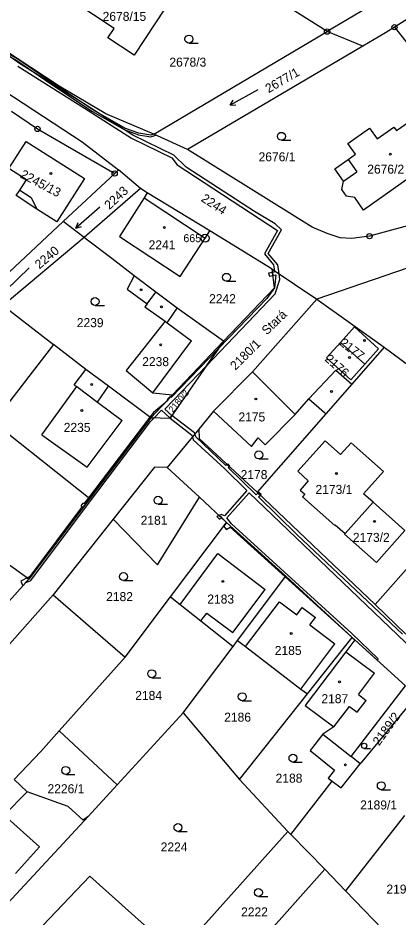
# Model space of a CAD drawing. Extents: x -562167 to -556918, y -1077891 to -1070763.
# Drawn here: x -560776.5 to -560704.7, y -1077589.8 to -1077420 of the extents above; entities that cross this region are included whole.
import ezdxf

# ---------------------------------------------------------------- set-up
doc = ezdxf.new("R2010")
doc.units = 0
for name, color, linetype in [('Hranice parcel', 7, 'Continuous'), ('Parcelní čísla', 7, 'Continuous'), ('Pop  PČ popisy', 7, 'Continuous'), ('Vnitřní kresba', 7, 'Continuous'), ('Věcná břemena k části', 7, 'Continuous'), ('Značky bodu BP', 7, 'Continuous'), ('Značky budov', 7, 'Continuous'), ('Značky kultur', 7, 'Continuous')]:
    doc.layers.add(name, color=color, linetype=linetype)

msp = doc.modelspace()

# ---------------------------------------------------------------- linework, layer by layer
at = {"layer": 'Hranice parcel'}
for p, q in [((-560718.13, -1077422.6), (-560741.25, -1077407.93)), ((-560750.84, -1077441.94), (-560718.13, -1077422.6)), ((-560711.41, -1077425.38), (-560718.13, -1077422.6)), ((-560711.41, -1077425.38), (-560744.45, -1077444.84)), ((-560744.45, -1077444.84), (-560750.84, -1077441.94)), ((-560757.47, -1077448.67), (-560758.22, -1077449.37)), ((-560753.37, -1077452.19), (-560757.47, -1077448.67)), ((-560758.22, -1077449.37), (-560767.94, -1077458.46)), ((-560753.37, -1077452.19), (-560763.95, -1077461.47)), ((-560752.08, -1077452.99), (-560753.37, -1077452.19)), ((-560740.26, -1077460.22), (-560752.08, -1077452.99)), ((-560767.94, -1077458.46), (-560778.08, -1077467.94)), ((-560763.95, -1077461.47), (-560767.94, -1077458.46)), ((-560728.52, -1077467.41), (-560740.26, -1077460.22)), ((-560763.95, -1077461.47), (-560779.27, -1077474.26)), ((-560697.73, -1077465.37), (-560720.07, -1077473.08)), ((-560728.52, -1077467.41), (-560720.07, -1077473.08)), ((-560779.27, -1077474.26), (-560769.74, -1077481.63)), ((-560720.07, -1077473.08), (-560707.36, -1077482.16)), ((-560747.28, -1077491.14), (-560737.69, -1077481.03)), ((-560711.02, -1077485.36), (-560715.6, -1077481.23)), ((-560769.74, -1077481.63), (-560781.07, -1077496.26)), ((-560707.36, -1077482.16), (-560682.61, -1077500.59)), ((-560751.4, -1077495.49), (-560747.28, -1077491.14)), ((-560739.56, -1077494.2), (-560742.36, -1077497.58)), ((-560718.37, -1077494.71), (-560731.36, -1077509.51)), ((-560781.07, -1077496.26), (-560762.93, -1077510.69)), ((-560762.93, -1077510.69), (-560751.4, -1077495.49)), ((-560742.36, -1077497.58), (-560748.29, -1077504.85)), ((-560748.29, -1077504.85), (-560742.24, -1077510.44)), ((-560731.36, -1077509.51), (-560709.04, -1077530.7)), ((-560774.45, -1077525.87), (-560762.93, -1077510.69)), ((-560742.24, -1077510.44), (-560737.1, -1077515.19)), ((-560714.73, -1077517.29), (-560709.46, -1077511.38)), ((-560758.48, -1077514.58), (-560769.81, -1077528.83)), ((-560747.68, -1077529.23), (-560737.1, -1077515.19)), ((-560737.1, -1077515.19), (-560725.93, -1077525.36)), ((-560696.13, -1077515.99), (-560709.04, -1077530.7)), ((-560774.45, -1077525.87), (-560782.82, -1077519.85)), ((-560735.04, -1077537.45), (-560725.93, -1077525.36)), ((-560725.93, -1077525.36), (-560713.41, -1077536.89)), ((-560769.81, -1077528.83), (-560756.25, -1077540.6)), ((-560756.25, -1077540.6), (-560747.68, -1077529.23)), ((-560709.04, -1077530.7), (-560703.28, -1077536.28)), ((-560721.86, -1077547.54), (-560713.41, -1077536.89)), ((-560713.41, -1077536.89), (-560712.89, -1077537.36)), ((-560712.89, -1077537.36), (-560703.35, -1077546.03)), ((-560745.31, -1077551.1), (-560735.88, -1077538.57)), ((-560735.88, -1077538.57), (-560735.04, -1077537.45)), ((-560756.25, -1077540.6), (-560768.67, -1077554.48)), ((-560734.66, -1077563.7), (-560721.86, -1077547.54)), ((-560701.28, -1077547.91), (-560711.88, -1077560.7)), ((-560757.75, -1077564.67), (-560745.31, -1077551.1)), ((-560745.31, -1077551.1), (-560734.66, -1077563.7)), ((-560768.67, -1077554.48), (-560757.75, -1077564.67)), ((-560734.66, -1077563.7), (-560725.53, -1077573.49)), ((-560724.98, -1077574.05), (-560717.2, -1077563.98)), ((-560757.75, -1077564.67), (-560763.25, -1077570.66)), ((-560703.5, -1077570.47), (-560714.63, -1077584.71)), ((-560725.53, -1077573.49), (-560744.02, -1077594.13)), ((-560725.53, -1077573.49), (-560724.98, -1077574.05)), ((-560718.57, -1077580.57), (-560724.98, -1077574.05)), ((-560718.57, -1077580.57), (-560733.72, -1077597.56)), ((-560714.63, -1077584.71), (-560718.57, -1077580.57)), ((-560714.63, -1077584.71), (-560705.92, -1077593.73))]:
    msp.add_line(p, q, dxfattribs=at)
for points in [[(-560877.62, -1077369.81), (-560869.17, -1077375.64), (-560821.56, -1077405.93), (-560764.33, -1077443.43), (-560757.47, -1077448.67)], [(-560668.72, -1077392.43), (-560686.84, -1077410.17), (-560705.42, -1077421.78)], [(-560758.31, -1077422), (-560766.1, -1077416.89), (-560761.45, -1077409.83), (-560748.66, -1077418.18), (-560754.53, -1077427.07), (-560759.49, -1077423.81), (-560758.31, -1077422)], [(-560705.88, -1077415.05), (-560710.42, -1077418.05), (-560718.13, -1077422.6)], [(-560750.84, -1077441.94), (-560759.89, -1077438.13), (-560768.71, -1077432.87), (-560787.2, -1077420.77)], [(-560705.42, -1077421.78), (-560707.11, -1077422.85), (-560711.41, -1077425.38)], [(-560705.42, -1077421.78), (-560691.8, -1077438.94), (-560686.3, -1077445)], [(-560777.7, -1077437.59), (-560772.79, -1077440.96), (-560758.22, -1077449.37)], [(-560695.32, -1077444.21), (-560700.44, -1077447.78), (-560700.05, -1077448.39), (-560711.25, -1077456.28), (-560712.91, -1077453.92), (-560714.45, -1077453.63), (-560715.32, -1077452.4), (-560715.05, -1077450.85), (-560716.69, -1077448.51), (-560714.16, -1077446.72), (-560712.77, -1077445.74), (-560714.2, -1077443.69), (-560710.11, -1077440.81), (-560708.66, -1077442.84), (-560705.51, -1077440.62), (-560705.02, -1077441.25), (-560699.9, -1077437.67), (-560695.32, -1077444.21)], [(-560776.11, -1077452.52), (-560774.86, -1077450.56), (-560778.19, -1077448.46), (-560774.9, -1077443.33), (-560763.93, -1077450.3), (-560769.13, -1077458.47), (-560772.89, -1077456.08), (-560776.78, -1077453.53), (-560776.11, -1077452.52)], [(-560685.68, -1077455.18), (-560689.59, -1077455.62), (-560710.13, -1077461.19), (-560713.49, -1077461.63), (-560715.68, -1077461.51), (-560718.09, -1077460.7), (-560720.94, -1077459.48), (-560744.45, -1077444.84)], [(-560752.08, -1077452.99), (-560752.68, -1077453.94), (-560757.32, -1077461.28), (-560745.85, -1077468.78), (-560741.15, -1077461.58), (-560740.26, -1077460.22)], [(-560754.57, -1077468.7), (-560758.77, -1077465.38), (-560763.57, -1077461.75), (-560763.95, -1077461.47)], [(-560737.69, -1077481.03), (-560728.04, -1077470.93), (-560728.52, -1077467.41)], [(-560754.57, -1077468.7), (-560755.89, -1077471.18), (-560752.1, -1077473.97), (-560752.51, -1077474.51), (-560748.68, -1077477.24), (-560756.03, -1077486.53), (-560751, -1077490.72), (-560747.28, -1077491.14)], [(-560737.69, -1077481.03), (-560746.4, -1077474.75), (-560750.45, -1077471.75), (-560754.57, -1077468.7)], [(-560720.07, -1077473.08), (-560732.22, -1077486.79), (-560739.56, -1077494.2)], [(-560715.6, -1077481.23), (-560712.99, -1077478.31), (-560708.41, -1077482.46), (-560711.02, -1077485.36)], [(-560737.69, -1077481.03), (-560747.84, -1077495.6), (-560751.4, -1077495.49)], [(-560711.02, -1077485.36), (-560713.64, -1077488.27), (-560718.23, -1077484.16), (-560715.6, -1077481.23)], [(-560751.4, -1077495.49), (-560759.39, -1077489.52), (-560763.68, -1077486.32), (-560769.74, -1077481.63)], [(-560707.36, -1077482.16), (-560713.48, -1077489.14), (-560718.37, -1077494.71)], [(-560739.56, -1077494.2), (-560732.41, -1077500.9), (-560731.17, -1077499.22), (-560729.82, -1077500.56), (-560724.13, -1077494.81), (-560721.58, -1077491.87), (-560718.63, -1077494.48), (-560718.37, -1077494.71)], [(-560742.36, -1077497.58), (-560742.29, -1077499.35), (-560731.36, -1077509.51)], [(-560709.46, -1077511.38), (-560711.27, -1077509.77), (-560707.51, -1077505.61), (-560713.61, -1077500.21), (-560715.59, -1077502.41), (-560718.49, -1077499.79), (-560723.68, -1077505.55), (-560721.68, -1077507.36), (-560723.24, -1077509.08), (-560722.35, -1077509.89), (-560722.76, -1077510.34), (-560716.67, -1077515.77), (-560716.58, -1077515.64), (-560714.73, -1077517.29)], [(-560748.29, -1077504.85), (-560750.68, -1077504.78), (-560758.48, -1077514.58)], [(-560758.48, -1077514.58), (-560750.12, -1077523.2), (-560742.24, -1077510.44)], [(-560714.73, -1077517.29), (-560714.83, -1077517.39), (-560708.83, -1077522.74), (-560703.46, -1077516.72), (-560709.46, -1077511.38)], [(-560795.12, -1077548.97), (-560794.92, -1077548.75), (-560774.45, -1077525.87)], [(-560769.81, -1077528.83), (-560803.23, -1077566.5), (-560803.72, -1077567.05)], [(-560747.68, -1077529.23), (-560745.88, -1077530.65), (-560741.95, -1077533.77), (-560735.88, -1077538.57)], [(-560712.89, -1077537.36), (-560714.62, -1077539.63), (-560722.28, -1077549.71), (-560716.84, -1077553.73), (-560718.96, -1077555.14), (-560721.35, -1077558.24), (-560716.73, -1077561.9), (-560717.9, -1077563.45), (-560717.2, -1077563.98)], [(-560735.04, -1077537.45), (-560733.55, -1077538.59), (-560723.06, -1077546.62), (-560721.86, -1077547.54)], [(-560711.88, -1077560.7), (-560713.62, -1077559.33), (-560703.35, -1077546.03)], [(-560777.2, -1077563.69), (-560772.17, -1077558.4), (-560768.67, -1077554.48)], [(-560717.2, -1077563.98), (-560715.49, -1077565.27), (-560711.88, -1077560.7)], [(-560763.25, -1077570.66), (-560764.19, -1077571.35), (-560767.01, -1077568.77), (-560774.76, -1077565.99), (-560777.2, -1077563.69)], [(-560763.25, -1077570.66), (-560767.95, -1077575.79), (-560780.07, -1077588.79)], [(-560746.38, -1077596.77), (-560748.38, -1077594.93), (-560762.88, -1077581.89), (-560774.38, -1077593.94)]]:
    msp.add_lwpolyline(points, dxfattribs=at)
at = {"layer": 'Vnitřní kresba'}
for p, q in [((-560714.16, -1077446.72), (-560712.49, -1077449.09)), ((-560715.05, -1077450.85), (-560712.49, -1077449.09)), ((-560776.11, -1077452.52), (-560773.96, -1077453.9)), ((-560773.96, -1077453.9), (-560772.89, -1077456.08)), ((-560752.68, -1077453.94), (-560741.15, -1077461.58)), ((-560752.1, -1077473.97), (-560750.45, -1077471.75)), ((-560748.29, -1077477.54), (-560746.4, -1077474.75)), ((-560748.68, -1077477.24), (-560748.29, -1077477.54)), ((-560748.29, -1077477.54), (-560743.75, -1077480.94)), ((-560751, -1077490.72), (-560743.75, -1077480.94)), ((-560765.84, -1077489.21), (-560763.68, -1077486.32)), ((-560732.22, -1077486.79), (-560724.13, -1077494.81)), ((-560721.58, -1077491.87), (-560716.5, -1077486.5)), ((-560716.5, -1077486.5), (-560713.48, -1077489.14)), ((-560771.99, -1077498.68), (-560765.36, -1077489.57)), ((-560765.84, -1077489.21), (-560765.36, -1077489.57)), ((-560765.36, -1077489.57), (-560761.47, -1077492.48)), ((-560761.47, -1077492.48), (-560759.39, -1077489.52)), ((-560761.47, -1077492.48), (-560756.8, -1077495.98)), ((-560763.41, -1077504.75), (-560756.8, -1077495.98)), ((-560771.99, -1077498.68), (-560763.41, -1077504.75)), ((-560745.88, -1077530.65), (-560738.73, -1077521.08)), ((-560738.73, -1077521.08), (-560729.81, -1077527.82)), ((-560735.89, -1077535.93), (-560729.81, -1077527.82)), ((-560733.55, -1077538.59), (-560727.11, -1077530.18)), ((-560727.11, -1077530.18), (-560723.87, -1077532.64)), ((-560723.87, -1077532.64), (-560722.82, -1077531.26)), ((-560722.82, -1077531.26), (-560720.32, -1077533.13)), ((-560741.95, -1077533.77), (-560740.81, -1077532.33)), ((-560740.81, -1077532.33), (-560735.89, -1077535.93)), ((-560721.38, -1077534.53), (-560720.32, -1077533.13)), ((-560721.38, -1077534.53), (-560716.7, -1077538.08)), ((-560723.06, -1077546.62), (-560716.7, -1077538.08)), ((-560714.62, -1077539.63), (-560709.18, -1077543.63)), ((-560712.22, -1077547.63), (-560709.18, -1077543.63)), ((-560712.46, -1077551.01), (-560710.73, -1077548.76)), ((-560712.22, -1077547.63), (-560710.73, -1077548.76)), ((-560716.84, -1077553.73), (-560713.93, -1077549.89)), ((-560713.93, -1077549.89), (-560712.46, -1077551.01)), ((-560718.96, -1077555.14), (-560713.62, -1077559.33)), ((-560779.06, -1077570.4), (-560774.76, -1077565.99)), ((-560779.06, -1077570.4), (-560772.4, -1077576.37)), ((-560776.92, -1077581.4), (-560772.4, -1077576.37))]:
    msp.add_line(p, q, dxfattribs=at)
at = {"layer": 'Věcná břemena k části'}
for points in [[(-560786, -1077421.56), (-560787.2, -1077420.77), (-560787.62, -1077420.5), (-560787.72, -1077420.66), (-560787.36, -1077420.89), (-560786.75, -1077422.28), (-560784.02, -1077423.94), (-560776.67, -1077428.04), (-560770.27, -1077432.44), (-560762.38, -1077437.71), (-560756.3, -1077441.14), (-560753.75, -1077442.06), (-560751.37, -1077442.48), (-560750.43, -1077442.12), (-560750.84, -1077441.94), (-560751.39, -1077442.17), (-560753.67, -1077441.76), (-560756.18, -1077440.86), (-560762.22, -1077437.45), (-560770.11, -1077432.2), (-560776.51, -1077427.78), (-560783.88, -1077423.68), (-560786.38, -1077422.16)], [(-560728.36, -1077468.61), (-560728.44, -1077468.02), (-560729.18, -1077468.15), (-560729.01, -1077468.73)], [(-560748.67, -1077492.61), (-560750.88, -1077494.44), (-560751.57, -1077495.36), (-560751.4, -1077495.49), (-560750.81, -1077495.51), (-560749.4, -1077494.02), (-560747.77, -1077495.5), (-560747.43, -1077495.01), (-560748.74, -1077493.82), (-560740.9, -1077485.63), (-560738.59, -1077482.32), (-560747.57, -1077491.61), (-560747.65, -1077491.53), (-560747.77, -1077491.41), (-560748.3, -1077491.99), (-560748.18, -1077492.09), (-560748.12, -1077492.15)], [(-560750.81, -1077495.51), (-560751.4, -1077495.49), (-560762.93, -1077510.69), (-560774.45, -1077525.87), (-560775.08, -1077526.58), (-560774.02, -1077526.14), (-560763.7, -1077512.35), (-560751.44, -1077496.18)], [(-560751.57, -1077495.36), (-560763.13, -1077510.53), (-560762.93, -1077510.69), (-560751.4, -1077495.49)], [(-560737.02, -1077504.25), (-560736.57, -1077504.66), (-560736.46, -1077504.56), (-560736.88, -1077504.13)], [(-560731.19, -1077509.67), (-560730.75, -1077510.09), (-560730.59, -1077509.94), (-560731.02, -1077509.52)], [(-560774.73, -1077525.67), (-560774.45, -1077525.87), (-560762.93, -1077510.69), (-560763.13, -1077510.53), (-560764.03, -1077511.71), (-560764.22, -1077511.56), (-560764.58, -1077512.04), (-560764.35, -1077512.22), (-560774.21, -1077525.4)], [(-560738.46, -1077514.55), (-560738.02, -1077514.34), (-560738.5, -1077513.9), (-560738.91, -1077514.09)], [(-560726.02, -1077525.47), (-560725.93, -1077525.36), (-560737.1, -1077515.19), (-560737.64, -1077515.91), (-560737.15, -1077516.55), (-560736.4, -1077516.06)], [(-560713.41, -1077536.89), (-560725.93, -1077525.36), (-560726.02, -1077525.47)], [(-560775.95, -1077526.28), (-560775.58, -1077527.13), (-560774.45, -1077525.87), (-560774.73, -1077525.67)]]:
    msp.add_lwpolyline(points, close=True, dxfattribs=at)
for points in [[(-560776.52, -1077429.14), (-560763.9, -1077437.02), (-560755.05, -1077442.69), (-560747.45, -1077446.43), (-560746.45, -1077447.77), (-560727.47, -1077460.12), (-560729.96, -1077464.54), (-560728.23, -1077466.6), (-560728.07, -1077467.71), (-560728.03, -1077467.94), (-560728.44, -1077468.02), (-560728.36, -1077468.61), (-560727.8, -1077468.51), (-560728.04, -1077470.93), (-560729.51, -1077472.93), (-560738.59, -1077482.32), (-560740.9, -1077485.63), (-560727.92, -1077472.08), (-560727.03, -1077469.39), (-560727.18, -1077468.31), (-560727.43, -1077466.62), (-560729.23, -1077464.47), (-560726.73, -1077460.02), (-560727.91, -1077458.89), (-560731.82, -1077456.57), (-560744.74, -1077448.17), (-560747.07, -1077445.94), (-560754.77, -1077442.16), (-560763.58, -1077436.51), (-560776.19, -1077428.63), (-560782.13, -1077424.44)], [(-560703.93, -1077536.26), (-560723.8, -1077517.56), (-560731.08, -1077510.38), (-560730.75, -1077510.09), (-560731.19, -1077509.67), (-560731.52, -1077509.97), (-560736.78, -1077504.85), (-560736.57, -1077504.66), (-560737.02, -1077504.25), (-560737.26, -1077504.48), (-560742.92, -1077499.07), (-560743.11, -1077498.5), (-560743.17, -1077498.3), (-560747.43, -1077495.01), (-560747.77, -1077495.5), (-560743.69, -1077498.66), (-560743.56, -1077499.05), (-560743.38, -1077499.6), (-560737.41, -1077505.07), (-560733.3, -1077509.18), (-560737.49, -1077513.92), (-560738.05, -1077513.69), (-560738.5, -1077513.9), (-560738.02, -1077514.34), (-560737.1, -1077515.19), (-560725.93, -1077525.36), (-560713.41, -1077536.89), (-560712.89, -1077537.36), (-560708.62, -1077541.24), (-560708.47, -1077540.91), (-560713.47, -1077536.12), (-560736.17, -1077515.47), (-560737.05, -1077514.32), (-560732.86, -1077509.6), (-560701.87, -1077539.21)]]:
    msp.add_lwpolyline(points, dxfattribs=at)
at = {"layer": 'Značky bodu BP'}
for centre, radius in [((-560705.42, -1077421.78), 0.5), ((-560705.42, -1077421.78), 0.0303), ((-560718.13, -1077422.6), 0.5), ((-560718.13, -1077422.6), 0.0303), ((-560772.79, -1077440.96), 0.5), ((-560772.79, -1077440.96), 0.0303), ((-560758.22, -1077449.37), 0.5), ((-560758.22, -1077449.37), 0.0303), ((-560741.15, -1077461.58), 0.75), ((-560710.13, -1077461.19), 0.5), ((-560741.15, -1077461.58), 0.03), ((-560710.13, -1077461.19), 0.0303)]:
    msp.add_circle(centre, radius, dxfattribs=at)
at = {"layer": 'Značky budov'}
for centre in [(-560706.2, -1077445.74), (-560770.24, -1077449.38), (-560748.85, -1077459.55), (-560753.24, -1077471.3), (-560749.41, -1077474.51), (-560711.1, -1077480.87), (-560749.54, -1077481.71), (-560713.89, -1077484.07), (-560762.56, -1077489.18), (-560717.3, -1077490.5), (-560731.59, -1077491.91), (-560764.4, -1077494.08), (-560716.38, -1077505.95), (-560709.19, -1077515), (-560737.78, -1077526.31), (-560724.89, -1077536.16), (-560715.8, -1077545.26), (-560714.69, -1077560.93)]:
    msp.add_circle(centre, 0.175, dxfattribs=at)
at = {"layer": 'Značky kultur'}
for p, q in [((-560744.2, -1077424.78), (-560742.45, -1077424.78)), ((-560731.2, -1077433.58), (-560736.44, -1077436.49)), ((-560736.44, -1077436.49), (-560735.83, -1077435.57)), ((-560736.44, -1077436.49), (-560735.34, -1077436.45)), ((-560726.75, -1077443.11), (-560725, -1077443.11)), ((-560761.02, -1077455.73), (-560765.55, -1077459.66)), ((-560765.55, -1077459.66), (-560765.14, -1077458.64)), ((-560765.55, -1077459.66), (-560764.49, -1077459.4)), ((-560774.35, -1077467.19), (-560778.67, -1077471.36)), ((-560737.11, -1077469.71), (-560735.36, -1077469.71)), ((-560761.92, -1077474.27), (-560760.17, -1077474.27)), ((-560731.02, -1077503.22), (-560729.27, -1077503.22)), ((-560750.03, -1077511.76), (-560748.28, -1077511.76)), ((-560756.55, -1077526.16), (-560754.8, -1077526.16)), ((-560751.23, -1077544.48), (-560749.48, -1077544.48)), ((-560734.14, -1077548.83), (-560732.39, -1077548.83)), ((-560711.12, -1077557.83), (-560709.95, -1077557.83)), ((-560724.57, -1077560.41), (-560722.82, -1077560.41)), ((-560767.46, -1077562.73), (-560765.71, -1077562.73)), ((-560707.9, -1077565.62), (-560706.15, -1077565.62)), ((-560746.27, -1077573.49), (-560744.52, -1077573.49)), ((-560731.09, -1077585.75), (-560729.34, -1077585.75))]:
    msp.add_line(p, q, dxfattribs=at)
for centre, radius in [((-560744.2, -1077424.03), 0.75), ((-560726.75, -1077442.36), 0.75), ((-560737.11, -1077468.96), 0.75), ((-560761.92, -1077473.52), 0.75), ((-560731.02, -1077502.47), 0.75), ((-560750.03, -1077511.01), 0.75), ((-560756.55, -1077525.41), 0.75), ((-560751.23, -1077543.73), 0.75), ((-560734.14, -1077548.08), 0.75), ((-560711.13, -1077557.33), 0.502), ((-560724.57, -1077559.66), 0.75), ((-560767.46, -1077561.98), 0.75), ((-560707.9, -1077564.87), 0.75), ((-560746.27, -1077572.74), 0.75), ((-560731.09, -1077585), 0.75)]:
    msp.add_circle(centre, radius, dxfattribs=at)

# ---------------------------------------------------------------- texts
at = {"layer": 'Parcelní čísla'}
for s, p in [('2678/15', (-560760.49, -1077420.59)), ('2678/3', (-560747.89, -1077429.22)), ('2676/1', (-560731.06, -1077447.08)), ('2676/2', (-560710.55, -1077449.41)), ('2241', (-560751.81, -1077463.68)), ('2242', (-560740.4, -1077473.84)), ('2239', (-560765.37, -1077478.36)), ('2238', (-560753.02, -1077485.71)), ('2175', (-560734.86, -1077496.15)), ('2235', (-560767.84, -1077498.12)), ('2178', (-560734.45, -1077507.02)), ('2173/1', (-560720.32, -1077509.82)), ('2181', (-560753.32, -1077515.64)), ('2173/2', (-560713.27, -1077518.87)), ('2182', (-560759.83, -1077530.04)), ('2183', (-560740.74, -1077530.5)), ('2185', (-560728.01, -1077540.2)), ('2184', (-560754.34, -1077548.68)), ('2187', (-560719.21, -1077549.29)), ('2186', (-560737.55, -1077552.78)), ('2188', (-560727.85, -1077564.29)), ('2226/1', (-560770.89, -1077566.28)), ('2189/1', (-560711.89, -1077569.34)), ('2224', (-560749.54, -1077577.26)), ('2191', (-560706.94, -1077585.21)), ('2222', (-560734.36, -1077589.51))]:
    msp.add_text(s, height=1.7, dxfattribs=at).set_placement(p)
for s, height, rotation, p in [('2677/1', 1.7, 30, (-560729.19, -1077434.25)), ('2245/13', 1.7, 332, (-560776.21, -1077450.04)), ('2243', 1.7, 43, (-560759.21, -1077456.29)), ('2244', 1.7, 327, (-560742.05, -1077454.49)), ('2240', 1.7, 40, (-560772.41, -1077467.47)), ('2180/1', 1.7, 45, (-560735.42, -1077486.59)), ('2177', 1.7, 322, (-560715.92, -1077481.61)), ('2176', 1.7, 318, (-560718.7, -1077484.56)), ('2180/2', 1.19, 50, (-560747.25, -1077494.55)), ('2189/2', 1.7, 54, (-560708.31, -1077557.42))]:
    msp.add_text(s, height=height, rotation=rotation, dxfattribs=at).set_placement(p)
at = {"layer": 'Pop  PČ popisy'}
msp.add_text('Stará', height=1.7, rotation=44, dxfattribs=at).set_placement((-560729.49, -1077479.93))
at = {"layer": 'Značky bodu BP'}
msp.add_text('665', height=1.5, dxfattribs=at).set_placement((-560745.25, -1077462.33))

doc.saveas('drawing.dxf')
